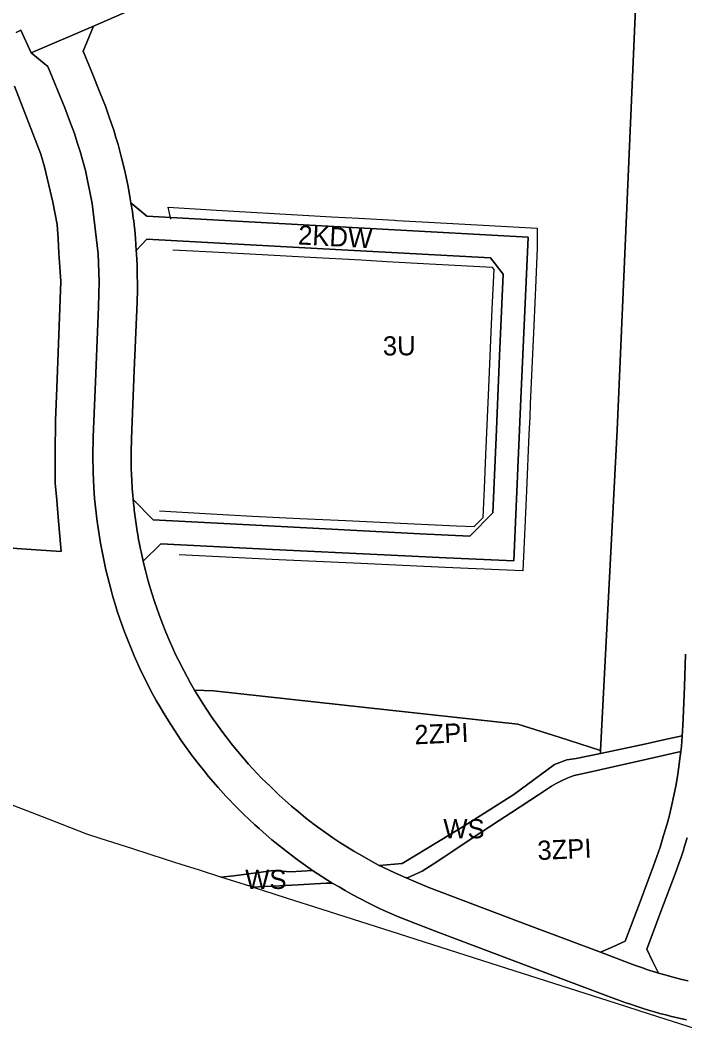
# Model space of a CAD drawing. Extents: x 7418021 to 7419743, y 5540231 to 5541685.
# Drawn here: x 7418418 to 7418764, y 5540422 to 5540950 of the extents above; entities that cross this region are included whole.
import ezdxf

# ---------------------------------------------------------------- set-up
doc = ezdxf.new("R2010")
doc.units = 0
for name, color, linetype in [('linie_rozgraniczajace', 7, 'Continuous'), ('linie_zabudowy_nieprzekraczalne', 7, 'Continuous'), ('oznaczenia_przeznaczen', 7, 'Continuous')]:
    doc.layers.add(name, color=color, linetype=linetype)

msp = doc.modelspace()

# ---------------------------------------------------------------- linework, layer by layer
at = {"layer": 'linie_rozgraniczajace'}
for points in [[(7418764.77, 5540619.88), (7418764.16, 5540602.99), (7418763.54, 5540586.11), (7418763.38, 5540582.71), (7418763.21, 5540579.7), (7418763.03, 5540577.24), (7418753.15, 5540575.08), (7418743.27, 5540572.92), (7418731.8, 5540570.48), (7418720.33, 5540568.05), (7418720.42, 5540569.59), (7418729.09, 5540736.57), (7418739.59, 5540980.91), (7418742.65, 5541062.87), (7418742.67, 5541063.2), (7418743.74, 5541085.5), (7418762.43, 5541093.5), (7418780.85, 5541101.4)], [(7418739.59, 5540980.91), (7418729.09, 5540736.57), (7418720.42, 5540569.59), (7418698.8, 5540576.48), (7418677.18, 5540583.37), (7418597.8, 5540592), (7418518.42, 5540600.64), (7418508.49, 5540601.02), (7418506.43, 5540604.69), (7418502.86, 5540611.28), (7418500.1, 5540616.7), (7418498.66, 5540619.68), (7418497.03, 5540623.25), (7418495.41, 5540626.82), (7418493.49, 5540631.34), (7418491.56, 5540636.2), (7418489.83, 5540640.81), (7418487.79, 5540646.68), (7418486.23, 5540651.53), (7418484.34, 5540657.94), (7418482.87, 5540663.45), (7418482.41, 5540665.26), (7418481.7, 5540668.26), (7418491, 5540677.41), (7418549.2, 5540674.46), (7418607.4, 5540671.52), (7418639.74, 5540670.03), (7418675.09, 5540668.49), (7418678.83, 5540752.88), (7418682.58, 5540837.27), (7418530.54, 5540845.67), (7418483.68, 5540848.29), (7418475.34, 5540855.21), (7418475.01, 5540857.18), (7418473.91, 5540863.65), (7418473.05, 5540867.72), (7418472.18, 5540871.8), (7418470.42, 5540878.66), (7418468.65, 5540885.52), (7418467.51, 5540889.26), (7418466.38, 5540893.01), (7418464.19, 5540899.3), (7418461.99, 5540905.59), (7418459.34, 5540912.35), (7418454.86, 5540923.27), (7418450.39, 5540934.2), (7418455.77, 5540947.39), (7418478.64, 5540957.19)], [(7418478.64, 5540957.19), (7418455.77, 5540947.39), (7418423.21, 5540933.43), (7418417.81, 5540945.3), (7418415.38, 5540944.05)], [(7418730, 5540439.31), (7418728.27, 5540439.94), (7418682.16, 5540457.27), (7418636.05, 5540474.6), (7418623.77, 5540479.32), (7418618.9, 5540481.27), (7418614.03, 5540483.22), (7418609.74, 5540485.13), (7418605.44, 5540487.04), (7418599.9, 5540489.79), (7418594.35, 5540492.55), (7418590.74, 5540494.52), (7418587.12, 5540496.5), (7418583.91, 5540498.39), (7418580.69, 5540500.27), (7418580.42, 5540500.44), (7418570.08, 5540507.03), (7418566.45, 5540509.56), (7418562.69, 5540512.23), (7418558.37, 5540515.44), (7418548.81, 5540523.05), (7418544.33, 5540526.88), (7418542.17, 5540528.81), (7418540.01, 5540530.74), (7418537.02, 5540533.49), (7418534.08, 5540536.36), (7418532.12, 5540538.26), (7418528.86, 5540541.56), (7418526.89, 5540543.64), (7418524.91, 5540545.72), (7418520.8, 5540550.25), (7418515.83, 5540556.04), (7418513.52, 5540558.89), (7418511.21, 5540561.74), (7418507.37, 5540566.73), (7418501.62, 5540574.76), (7418496.08, 5540583.07), (7418492.31, 5540589.19), (7418490.44, 5540592.42), (7418488.56, 5540595.66), (7418485.63, 5540601.05), (7418483.41, 5540605.34), (7418480.75, 5540610.76), (7418477.05, 5540618.92), (7418472.01, 5540631.39), (7418469.55, 5540638.29), (7418468.23, 5540642.14), (7418467.06, 5540645.91), (7418465.9, 5540649.69), (7418464.95, 5540653.09), (7418462.22, 5540663.78), (7418459.39, 5540677.61), (7418457.65, 5540689.04), (7418456.38, 5540700.92), (7418455.95, 5540706.78), (7418455.59, 5540714.53), (7418455.46, 5540723.16), (7418455.67, 5540733.07), (7418456.34, 5540749.55), (7418456.83, 5540761.74), (7418458.41, 5540800.99), (7418458.7, 5540814.09), (7418458.28, 5540828.54), (7418455.19, 5540854.78), (7418451.55, 5540872.11), (7418448.85, 5540881.97), (7418447.36, 5540886.66), (7418445.86, 5540891.36), (7418443.35, 5540898.06), (7418440.83, 5540904.77), (7418432.01, 5540926.32), (7418423.21, 5540933.43), (7418455.77, 5540947.39)], [(7418455.77, 5540947.39), (7418450.39, 5540934.2), (7418454.86, 5540923.27), (7418459.34, 5540912.35), (7418461.99, 5540905.59), (7418464.19, 5540899.3), (7418466.38, 5540893.01), (7418467.51, 5540889.26), (7418468.65, 5540885.52), (7418470.42, 5540878.66), (7418472.18, 5540871.8), (7418473.05, 5540867.72), (7418473.91, 5540863.65), (7418475.01, 5540857.18), (7418475.34, 5540855.21), (7418476.1, 5540850.7), (7418476.57, 5540847.09), (7418476.78, 5540845.93), (7418477.03, 5540843.47), (7418477.29, 5540841.02), (7418477.72, 5540836.58), (7418478.14, 5540830.29), (7418478.24, 5540828.64), (7418478.58, 5540822.7), (7418478.65, 5540817.71), (7418478.73, 5540812.73), (7418478.68, 5540809.86), (7418478.52, 5540803.36), (7418477.09, 5540767.82), (7418475.66, 5540732.27), (7418475.61, 5540730.94), (7418475.56, 5540729.61), (7418475.52, 5540727.72), (7418475.48, 5540725.82), (7418475.47, 5540723.84), (7418475.46, 5540721.86), (7418475.5, 5540719.32), (7418475.53, 5540716.78), (7418475.64, 5540713.33), (7418475.8, 5540710.31), (7418476.03, 5540706.14), (7418476.3, 5540702.51), (7418476.49, 5540700.53), (7418476.67, 5540698.56), (7418476.81, 5540697.23), (7418476.95, 5540695.91), (7418476.99, 5540695.51), (7418477.1, 5540694.57), (7418477.17, 5540694.02), (7418477.37, 5540692.41), (7418478.04, 5540687.54), (7418478.42, 5540685.09), (7418478.64, 5540683.69), (7418478.88, 5540682.28), (7418479.33, 5540679.61), (7418479.65, 5540677.95), (7418479.98, 5540676.28), (7418480.31, 5540674.62), (7418480.63, 5540673.09), (7418480.95, 5540671.56), (7418481.7, 5540668.26), (7418482.41, 5540665.26), (7418482.87, 5540663.45), (7418484.34, 5540657.94), (7418486.23, 5540651.53), (7418487.79, 5540646.68), (7418489.83, 5540640.81), (7418491.56, 5540636.2), (7418493.49, 5540631.34), (7418495.41, 5540626.82), (7418497.03, 5540623.25), (7418498.66, 5540619.68), (7418500.1, 5540616.7), (7418502.86, 5540611.28), (7418506.43, 5540604.69), (7418508.49, 5540601.02), (7418512.88, 5540593.98), (7418517.46, 5540587.06), (7418522.78, 5540579.6), (7418528.4, 5540572.32), (7418533.95, 5540565.65), (7418536.7, 5540562.47), (7418543.48, 5540555.21), (7418548.09, 5540550.73), (7418552.69, 5540546.25), (7418555.88, 5540543.41), (7418559.06, 5540540.57), (7418562.73, 5540537.54), (7418566.4, 5540534.51), (7418570.97, 5540530.98), (7418574.01, 5540528.77), (7418577.04, 5540526.56), (7418580.73, 5540524.05), (7418584.41, 5540521.55), (7418587.99, 5540519.31), (7418591.56, 5540517.07), (7418597.22, 5540513.86), (7418602.89, 5540510.66), (7418604.92, 5540509.64), (7418606.49, 5540508.85)], [(7418415.38, 5540944.05), (7418417.81, 5540945.3), (7418423.21, 5540933.43), (7418432.01, 5540926.32), (7418440.83, 5540904.77), (7418443.35, 5540898.06), (7418445.86, 5540891.36), (7418447.36, 5540886.66), (7418448.85, 5540881.97), (7418451.55, 5540872.11), (7418455.19, 5540854.78), (7418458.28, 5540828.54), (7418458.7, 5540814.09), (7418458.41, 5540800.99), (7418456.83, 5540761.74), (7418456.34, 5540749.55), (7418455.67, 5540733.07), (7418455.46, 5540723.16), (7418455.59, 5540714.53), (7418455.95, 5540706.78), (7418456.38, 5540700.92), (7418457.65, 5540689.04), (7418459.39, 5540677.61), (7418462.22, 5540663.78), (7418464.95, 5540653.09), (7418465.9, 5540649.69), (7418467.06, 5540645.91), (7418468.23, 5540642.14), (7418469.55, 5540638.29), (7418472.01, 5540631.39), (7418477.05, 5540618.92), (7418480.75, 5540610.76), (7418483.41, 5540605.34), (7418485.63, 5540601.05), (7418488.56, 5540595.66), (7418490.44, 5540592.42), (7418492.31, 5540589.19), (7418496.08, 5540583.07), (7418501.62, 5540574.76), (7418507.37, 5540566.73), (7418511.21, 5540561.74), (7418513.52, 5540558.89), (7418515.83, 5540556.04), (7418520.8, 5540550.25), (7418524.91, 5540545.72), (7418526.89, 5540543.64)], [(7418414.61, 5540915.96), (7418428.31, 5540880.55), (7418430.23, 5540873.89), (7418434.5, 5540855.57), (7418436.86, 5540843.92), (7418437.32, 5540836.46), (7418437.78, 5540829.01), (7418438.24, 5540821.56), (7418438.7, 5540814.1), (7418437.32, 5540777.16), (7418436.63, 5540758.69), (7418435.95, 5540741.74), (7418435.87, 5540724.63), (7418435.8, 5540709.03), (7418436.59, 5540700.17), (7418437.38, 5540691.3), (7418438.96, 5540673.4), (7418423.36, 5540674.41), (7418375.61, 5540677.74)], [(7418375.61, 5540677.74), (7418423.36, 5540674.41), (7418438.96, 5540673.4), (7418437.38, 5540691.3), (7418436.59, 5540700.17), (7418435.8, 5540709.03), (7418435.87, 5540724.63), (7418435.95, 5540741.74), (7418436.63, 5540758.69), (7418437.32, 5540777.16), (7418438.7, 5540814.1), (7418438.24, 5540821.56), (7418437.78, 5540829.01), (7418437.32, 5540836.46), (7418436.86, 5540843.92), (7418434.5, 5540855.57), (7418430.23, 5540873.89), (7418428.31, 5540880.55), (7418414.61, 5540915.96)], [(7418765.59, 5540523.96), (7418764.22, 5540519.61), (7418763.58, 5540517.59), (7418762.93, 5540515.57), (7418762.19, 5540513.4), (7418761.46, 5540511.22), (7418760.37, 5540508.21), (7418759.27, 5540505.19), (7418751.88, 5540485.58), (7418744.49, 5540465.97), (7418747.51, 5540459.74), (7418750.54, 5540453.5), (7418748.59, 5540454.11), (7418746.7, 5540454.7), (7418744.52, 5540455.42), (7418742.35, 5540456.14), (7418738.63, 5540457.44), (7418735.32, 5540458.66), (7418720.35, 5540464.3), (7418726.79, 5540467.22), (7418733.24, 5540470.13), (7418740.64, 5540489.78), (7418748.04, 5540509.43), (7418749.75, 5540514.26), (7418751.46, 5540519.09), (7418753.3, 5540525.22), (7418755.14, 5540531.36), (7418756.29, 5540535.91), (7418757.44, 5540540.47), (7418758.6, 5540546.12), (7418759.77, 5540551.76), (7418760.63, 5540557.13), (7418761.48, 5540562.51), (7418761.83, 5540565.35), (7418762.28, 5540569.08), (7418762.39, 5540570.1), (7418762.59, 5540572), (7418762.77, 5540574.12), (7418763.03, 5540577.24), (7418763.21, 5540579.7), (7418763.38, 5540582.71), (7418763.54, 5540586.11), (7418764.16, 5540602.99), (7418764.77, 5540619.88)], [(7418439.46, 5540530.91), (7418426.01, 5540536.16), (7418412.56, 5540541.41)], [(7418526.89, 5540543.64), (7418528.86, 5540541.56), (7418532.12, 5540538.26), (7418534.08, 5540536.36), (7418537.02, 5540533.49), (7418540.01, 5540530.74), (7418542.17, 5540528.81), (7418544.33, 5540526.88), (7418548.81, 5540523.05), (7418558.37, 5540515.44), (7418562.69, 5540512.23), (7418566.45, 5540509.56), (7418570.08, 5540507.03), (7418564.31, 5540506.64), (7418558.55, 5540506.24), (7418549.77, 5540507), (7418529.11, 5540504.12), (7418522.22, 5540503.56), (7418510.68, 5540507.25), (7418502.03, 5540510.01), (7418493.39, 5540512.77), (7418476.3, 5540518.22), (7418459.22, 5540523.68), (7418452.3, 5540525.89), (7418439.46, 5540530.91)], [(7418766.16, 5540449.38), (7418762.74, 5540450.16), (7418758.27, 5540451.3), (7418753.96, 5540452.49), (7418750.54, 5540453.5), (7418747.51, 5540459.74), (7418744.49, 5540465.97), (7418751.88, 5540485.58), (7418759.27, 5540505.19), (7418760.37, 5540508.21), (7418761.46, 5540511.22), (7418762.19, 5540513.4), (7418762.93, 5540515.57), (7418763.58, 5540517.59), (7418764.22, 5540519.61), (7418765.59, 5540523.96)], [(7418606.49, 5540508.85), (7418610.7, 5540506.82), (7418614.92, 5540504.8), (7418618.96, 5540503.08), (7418622.87, 5540501.42), (7418630.82, 5540498.04), (7418683.07, 5540478.35), (7418720.35, 5540464.3), (7418735.32, 5540458.66), (7418738.63, 5540457.44), (7418742.35, 5540456.14), (7418744.52, 5540455.42), (7418746.7, 5540454.7), (7418748.59, 5540454.11), (7418750.54, 5540453.5), (7418753.96, 5540452.49), (7418758.27, 5540451.3), (7418762.74, 5540450.16), (7418766.16, 5540449.38)], [(7418778.14, 5540421.84), (7418745.92, 5540432.13), (7418728.63, 5540437.65), (7418695.99, 5540448.07), (7418663.36, 5540458.49), (7418619.24, 5540472.58), (7418575.12, 5540486.67), (7418556.52, 5540492.61), (7418538.74, 5540498.29), (7418538.84, 5540498.29), (7418539.87, 5540498.34), (7418544.16, 5540498.55), (7418549.59, 5540498.81), (7418556.06, 5540499.17), (7418562.53, 5540499.53), (7418568.35, 5540499.86), (7418574.17, 5540500.19), (7418577.3, 5540500.32), (7418580.42, 5540500.44), (7418580.69, 5540500.27), (7418583.91, 5540498.39), (7418587.12, 5540496.5), (7418590.74, 5540494.52), (7418594.35, 5540492.55), (7418599.9, 5540489.79), (7418605.44, 5540487.04), (7418609.74, 5540485.13), (7418614.03, 5540483.22), (7418618.9, 5540481.27), (7418623.77, 5540479.32), (7418636.05, 5540474.6), (7418682.16, 5540457.27), (7418728.27, 5540439.94), (7418730, 5540439.31), (7418731.73, 5540438.67), (7418733.61, 5540438.01), (7418735.48, 5540437.35), (7418739.56, 5540435.97), (7418743.18, 5540434.85), (7418745.93, 5540434), (7418748.61, 5540433.24), (7418751.3, 5540432.47), (7418754.39, 5540431.67), (7418757.47, 5540430.86), (7418761.34, 5540429.97), (7418765.21, 5540429.07)], [(7418765.21, 5540429.07), (7418761.34, 5540429.97), (7418757.47, 5540430.86), (7418754.39, 5540431.67), (7418751.3, 5540432.47), (7418748.61, 5540433.24), (7418745.93, 5540434), (7418743.18, 5540434.85), (7418739.56, 5540435.97), (7418735.48, 5540437.35), (7418733.61, 5540438.01), (7418731.73, 5540438.67), (7418730, 5540439.31)]]:
    msp.add_lwpolyline(points, dxfattribs=at)
for points in [[(7418475.34, 5540855.21), (7418483.68, 5540848.29), (7418530.54, 5540845.67), (7418682.58, 5540837.27), (7418678.83, 5540752.88), (7418675.09, 5540668.49), (7418639.74, 5540670.03), (7418607.4, 5540671.52), (7418549.2, 5540674.46), (7418491, 5540677.41), (7418481.7, 5540668.26), (7418480.95, 5540671.56), (7418480.63, 5540673.09), (7418480.31, 5540674.62), (7418479.98, 5540676.28), (7418479.65, 5540677.95), (7418479.33, 5540679.61), (7418478.88, 5540682.28), (7418478.64, 5540683.69), (7418478.42, 5540685.09), (7418478.04, 5540687.54), (7418477.37, 5540692.41), (7418477.17, 5540694.02), (7418477.1, 5540694.57), (7418476.99, 5540695.51), (7418476.95, 5540695.91), (7418476.81, 5540697.23), (7418476.67, 5540698.56), (7418476.49, 5540700.53), (7418487.01, 5540689.79), (7418543.77, 5540686.82), (7418626.33, 5540682.63), (7418652.12, 5540681.42), (7418664.19, 5540693.49), (7418665.93, 5540732.81), (7418667.71, 5540775.36), (7418669.5, 5540817.92), (7418662.87, 5540826.53), (7418575.58, 5540831.27), (7418483.68, 5540836.26), (7418478.14, 5540830.29), (7418477.72, 5540836.58), (7418477.29, 5540841.02), (7418477.03, 5540843.47), (7418476.78, 5540845.93), (7418476.57, 5540847.09), (7418476.1, 5540850.7)], [(7418478.14, 5540830.29), (7418483.68, 5540836.26), (7418575.58, 5540831.27), (7418662.87, 5540826.53), (7418669.5, 5540817.92), (7418667.71, 5540775.36), (7418665.93, 5540732.81), (7418664.19, 5540693.49), (7418652.12, 5540681.42), (7418626.33, 5540682.63), (7418543.77, 5540686.82), (7418487.01, 5540689.79), (7418476.49, 5540700.53), (7418476.3, 5540702.51), (7418476.03, 5540706.14), (7418475.8, 5540710.31), (7418475.64, 5540713.33), (7418475.53, 5540716.78), (7418475.5, 5540719.32), (7418475.46, 5540721.86), (7418475.47, 5540723.84), (7418475.48, 5540725.82), (7418475.52, 5540727.72), (7418475.56, 5540729.61), (7418475.61, 5540730.94), (7418475.66, 5540732.27), (7418477.09, 5540767.82), (7418478.52, 5540803.36), (7418478.68, 5540809.86), (7418478.73, 5540812.73), (7418478.65, 5540817.71), (7418478.58, 5540822.7), (7418478.24, 5540828.64)], [(7418508.49, 5540601.02), (7418518.42, 5540600.64), (7418597.8, 5540592), (7418677.18, 5540583.37), (7418698.8, 5540576.48), (7418720.42, 5540569.59), (7418720.33, 5540568.05), (7418707.7, 5540565.39), (7418702.71, 5540564.69), (7418696.41, 5540562.22), (7418675.16, 5540546.61), (7418649.08, 5540530.1), (7418616.9, 5540510.58), (7418604.92, 5540509.64), (7418602.89, 5540510.66), (7418597.22, 5540513.86), (7418591.56, 5540517.07), (7418587.99, 5540519.31), (7418584.41, 5540521.55), (7418580.73, 5540524.05), (7418577.04, 5540526.56), (7418574.01, 5540528.77), (7418570.97, 5540530.98), (7418566.4, 5540534.51), (7418562.73, 5540537.54), (7418559.06, 5540540.57), (7418555.88, 5540543.41), (7418552.69, 5540546.25), (7418548.09, 5540550.73), (7418543.48, 5540555.21), (7418536.7, 5540562.47), (7418533.95, 5540565.65), (7418528.4, 5540572.32), (7418522.78, 5540579.6), (7418517.46, 5540587.06), (7418512.88, 5540593.98)], [(7418763.03, 5540577.24), (7418762.77, 5540574.12), (7418762.59, 5540572), (7418762.39, 5540570.1), (7418762.28, 5540569.08), (7418740.85, 5540564.25), (7418713.02, 5540557.93), (7418706.61, 5540556.44), (7418704.78, 5540555.77), (7418702.94, 5540555.1), (7418700.07, 5540553.69), (7418698.63, 5540552.99), (7418697.2, 5540552.28), (7418694.79, 5540550.87), (7418687.95, 5540546.38), (7418673.9, 5540537.17), (7418667.49, 5540532.96), (7418652.42, 5540523.06), (7418643.25, 5540517.04), (7418638.55, 5540513.96), (7418632.96, 5540510.3), (7418627.36, 5540506.63), (7418625.36, 5540505.68), (7418623.42, 5540504.84), (7418621.49, 5540503.99), (7418619.59, 5540503.23), (7418618.96, 5540503.08), (7418614.92, 5540504.8), (7418610.7, 5540506.82), (7418606.49, 5540508.85), (7418604.92, 5540509.64), (7418616.9, 5540510.58), (7418649.08, 5540530.1), (7418675.16, 5540546.61), (7418696.41, 5540562.22), (7418702.71, 5540564.69), (7418707.7, 5540565.39), (7418720.33, 5540568.05), (7418731.8, 5540570.48), (7418743.27, 5540572.92), (7418753.15, 5540575.08)], [(7418762.28, 5540569.08), (7418761.83, 5540565.35), (7418761.48, 5540562.51), (7418760.63, 5540557.13), (7418759.77, 5540551.76), (7418758.6, 5540546.12), (7418757.44, 5540540.47), (7418756.29, 5540535.91), (7418755.14, 5540531.36), (7418753.3, 5540525.22), (7418751.46, 5540519.09), (7418749.75, 5540514.26), (7418748.04, 5540509.43), (7418740.64, 5540489.78), (7418733.24, 5540470.13), (7418726.79, 5540467.22), (7418720.35, 5540464.3), (7418683.07, 5540478.35), (7418630.82, 5540498.04), (7418622.87, 5540501.42), (7418618.96, 5540503.08), (7418619.59, 5540503.23), (7418621.49, 5540503.99), (7418623.42, 5540504.84), (7418625.36, 5540505.68), (7418627.36, 5540506.63), (7418632.96, 5540510.3), (7418638.55, 5540513.96), (7418643.25, 5540517.04), (7418652.42, 5540523.06), (7418667.49, 5540532.96), (7418673.9, 5540537.17), (7418687.95, 5540546.38), (7418694.79, 5540550.87), (7418697.2, 5540552.28), (7418698.63, 5540552.99), (7418700.07, 5540553.69), (7418702.94, 5540555.1), (7418704.78, 5540555.77), (7418706.61, 5540556.44), (7418713.02, 5540557.93), (7418740.85, 5540564.25)], [(7418522.22, 5540503.56), (7418529.11, 5540504.12), (7418549.77, 5540507), (7418558.55, 5540506.24), (7418564.31, 5540506.64), (7418570.08, 5540507.03), (7418580.42, 5540500.44), (7418577.3, 5540500.32), (7418574.17, 5540500.19), (7418568.35, 5540499.86), (7418562.53, 5540499.53), (7418556.06, 5540499.17), (7418549.59, 5540498.81), (7418544.16, 5540498.55), (7418539.87, 5540498.34), (7418538.84, 5540498.29), (7418538.74, 5540498.29), (7418537.92, 5540498.55)]]:
    msp.add_lwpolyline(points, close=True, dxfattribs=at)
at = {"layer": 'linie_zabudowy_nieprzekraczalne'}
for points in [[(7418496.13, 5540846.59), (7418494.81, 5540852.93)], [(7418494.81, 5540852.93), (7418520.02, 5540851.27)], [(7418520.02, 5540851.27), (7418568.12, 5540848.58)], [(7418568.12, 5540848.58), (7418579.96, 5540847.92)], [(7418579.96, 5540847.92), (7418594.34, 5540847.12)], [(7418594.34, 5540847.12), (7418612.84, 5540846.09)], [(7418612.84, 5540846.09), (7418614.01, 5540846.02)], [(7418614.01, 5540846.02), (7418630.55, 5540845.1)], [(7418630.55, 5540845.1), (7418662.23, 5540843.33)], [(7418662.23, 5540843.33), (7418687.37, 5540841.93)], [(7418687.37, 5540841.93), (7418687.34, 5540831.68)], [(7418504.17, 5540830.15), (7418497.25, 5540830.53)], [(7418517.85, 5540829.41), (7418504.17, 5540830.15)], [(7418543.76, 5540828), (7418517.85, 5540829.41)], [(7418687.34, 5540831.68), (7418686.59, 5540814.9)], [(7418568.84, 5540826.63), (7418543.76, 5540828)], [(7418595.51, 5540825.19), (7418568.84, 5540826.63)], [(7418608.81, 5540824.46), (7418595.51, 5540825.19)], [(7418631.15, 5540823.25), (7418608.81, 5540824.46)], [(7418663.99, 5540821.46), (7418631.15, 5540823.25)], [(7418663.91, 5540799.93), (7418664.81, 5540820.33)], [(7418664.81, 5540820.33), (7418663.99, 5540821.46)], [(7418686.59, 5540814.9), (7418685.54, 5540791.15)], [(7418661.91, 5540754.89), (7418663.91, 5540799.93)], [(7418685.54, 5540791.15), (7418683.72, 5540750.29)], [(7418660.52, 5540723.67), (7418661.91, 5540754.89)], [(7418683.72, 5540750.29), (7418683.42, 5540743.43)], [(7418683.42, 5540743.43), (7418683.02, 5540734.51)], [(7418683.02, 5540734.51), (7418681.71, 5540704.91)], [(7418659.76, 5540706.38), (7418660.52, 5540723.67)], [(7418659.09, 5540690.99), (7418659.76, 5540706.38)], [(7418681.71, 5540704.91), (7418680.52, 5540678.17)], [(7418490.24, 5540694.56), (7418514.14, 5540693.18)], [(7418514.14, 5540693.18), (7418538.69, 5540691.76)], [(7418538.69, 5540691.76), (7418563.47, 5540690.56)], [(7418563.47, 5540690.56), (7418587.41, 5540689.46)], [(7418587.41, 5540689.46), (7418626.82, 5540687.64)], [(7418626.82, 5540687.64), (7418645.16, 5540686.8)], [(7418645.16, 5540686.8), (7418654.35, 5540686.37)], [(7418654.35, 5540686.37), (7418659.09, 5540690.99)], [(7418680.52, 5540678.17), (7418679.86, 5540663.32)], [(7418552.53, 5540669.04), (7418500.59, 5540671.55)], [(7418595.34, 5540667.07), (7418552.53, 5540669.04)], [(7418620.87, 5540665.89), (7418595.34, 5540667.07)], [(7418639.27, 5540665.05), (7418620.87, 5540665.89)], [(7418667.54, 5540663.74), (7418639.27, 5540665.05)], [(7418679.86, 5540663.32), (7418667.54, 5540663.74)]]:
    msp.add_lwpolyline(points, dxfattribs=at)

# ---------------------------------------------------------------- texts
at = {"layer": 'oznaczenia_przeznaczen'}
for s, rotation, p in [('2KDW', 356.9424, (7418562.37, 5540833.52)), ('3U', 0.4836, (7418606.84, 5540775.55)), ('2ZPI', 2.669, (7418623.47, 5540572.73)), ('3ZPI', 2.669, (7418687.67, 5540512.4))]:
    msp.add_text(s, height=10, rotation=rotation, dxfattribs=at).set_placement(p)
for p in [(7418638.36, 5540523.76), (7418534.97, 5540497.33)]:
    msp.add_text('WS', height=10, dxfattribs=at).set_placement(p)

doc.saveas('drawing.dxf')
